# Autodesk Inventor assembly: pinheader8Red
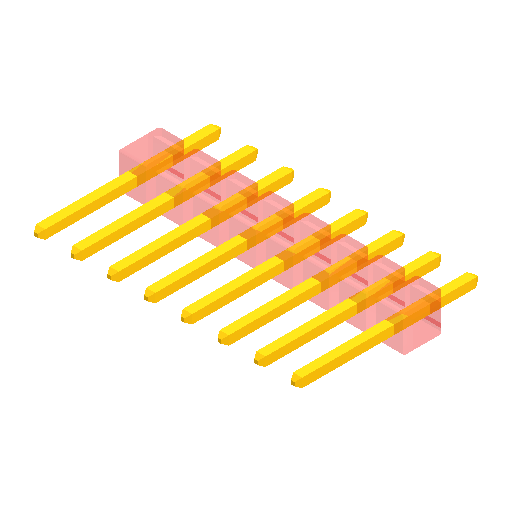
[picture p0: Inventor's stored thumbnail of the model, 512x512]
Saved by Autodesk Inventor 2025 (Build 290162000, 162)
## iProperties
Created: 2025-05
Part Number: pinheader8Red
Document SubType Name: Assembly
Designer: R5800u
Author: R5800u
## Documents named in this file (3)
- C:\Users\R5800u\Desktop\drone\c3\ESP32-C3 Super Mini breakout expansion board module -Assembly\pinheader8Red.iam
- C:\Users\R5800u\Desktop\drone\c3\ESP32-C3 Super Mini breakout expansion board module -Assembly\COMPOUND_2.iam
- C:\Users\R5800u\Desktop\drone\c3\ESP32-C3 Super Mini breakout expansion board module -Assembly\COMPOUND_3.iam
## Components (2 placed, 2 different names)
1. 29 [sub-assembly]
2. 38 [sub-assembly]
